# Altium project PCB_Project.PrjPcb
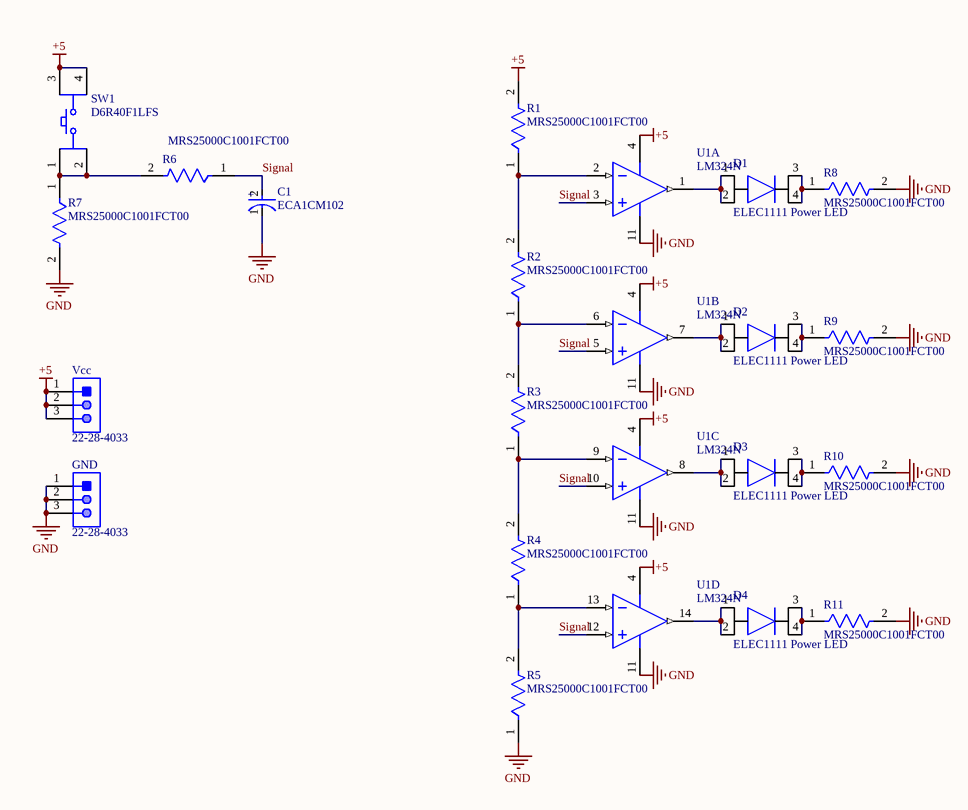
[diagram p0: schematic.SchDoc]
1 sheet, 20 parts. Net scope: global (net labels, ports and power ports of the same name join across sheets).

## Sheet schematic.SchDoc
size A4; SheetNumber: 1; SheetTotal: 1

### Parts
C1  ECA1CM102  [FP-RAD-TH-D_10_0_5-L_16_1-MFG]
D1  ELEC1111 Power LED  [ELEC1111_PowerLED]
D2  ELEC1111 Power LED  [ELEC1111_PowerLED]
D3  ELEC1111 Power LED  [ELEC1111_PowerLED]
D4  ELEC1111 Power LED  [ELEC1111_PowerLED]
GND  22-28-4033  [MOLX-22-28-4033_V]
R1  MRS25000C1001FCT00  [FP-MRS25-MFG]
R2  MRS25000C1001FCT00  [FP-MRS25-MFG]
R3  MRS25000C1001FCT00  [FP-MRS25-MFG]
R4  MRS25000C1001FCT00  [FP-MRS25-MFG]
R5  MRS25000C1001FCT00  [FP-MRS25-MFG]
R6  MRS25000C1001FCT00  [FP-MRS25-MFG]
R7  MRS25000C1001FCT00  [FP-MRS25-MFG]
R8  MRS25000C1001FCT00  [FP-MRS25-MFG]
R9  MRS25000C1001FCT00  [FP-MRS25-MFG]
R10  MRS25000C1001FCT00  [FP-MRS25-MFG]
R11  MRS25000C1001FCT00  [FP-MRS25-MFG]
SW1  D6R40F1LFS  [FP-D6R40F1LFS-MFG]
U1  LM324N  [N0014A]  (parts A,B,C,D of 4)
Vcc  22-28-4033  [MOLX-22-28-4033_V]

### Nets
+5: R1.2 SW1.3 SW1.4 U1.4(V+) Vcc.1 Vcc.2 Vcc.3
GND: C1.1(C) GND.1 GND.2 GND.3 R5.1 R7.2 R8.2 R9.2 R10.2 R11.2 U1.11(GND)
Signal: C1.2(A) R6.1 U1.3(IN1+) U1.5(IN2+) U1.10(IN3+) U1.12(IN4+)
NetD1_1: D1.1 D1.2 U1.1(OUT1)
NetD1_3: D1.3 D1.4 R8.1
NetD2_1: D2.1 D2.2 U1.7(OUT2)
NetD2_3: D2.3 D2.4 R9.1
NetD3_1: D3.1 D3.2 U1.8(OUT3)
NetD3_3: D3.3 D3.4 R10.1
NetD4_1: D4.1 D4.2 U1.14(OUT4)
NetD4_3: D4.3 D4.4 R11.1
NetR1_1: R1.1 R2.2 U1.2(IN1-)
NetR2_1: R2.1 R3.2 U1.6(IN2-)
NetR3_1: R3.1 R4.2 U1.9(IN3-)
NetR4_1: R4.1 R5.2 U1.13(IN4-)
NetR6_2: R6.2 R7.1 SW1.1 SW1.2

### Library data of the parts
C1 = CMP-05427-001524-1: Aluminum Electrolytic Capacitors (Radial Lead Type) 1000uF ±20% 16V; Life (Hours): 2000Hour; Ripple Current (AC): 680mA; Polarity: Polar; Lead/Base Style: Straight; Lead Diameter: 0.6mm; Capacitance: 1mF; Leakage Current: 3uA; Dissipation Factor: 0.2%
D1-D4 = ELEC1111 Power LED: An LED used in ELEC1111
GND Vcc = CMP-1676-00001-5: Male Header, Pitch 2.54 mm, 1 x 3 Position, Height 8.38 mm, Tail Length 3.18 mm, RoHS, Bulk; Manufacturer: Molex; Rows: 1; Voltage Rating: 250 V; Current Rating: 4 A
R1-R11 = CMP-02408-000051-1: RES 1K OHM 0.6W 1% AXIAL; Power Rating: 600mW; Lead Diameter: 0.6mm; Voltage Rating (DC): 350V; Resistance: 1kR; Temperature Coefficient: 50ppm/°C
SW1 = CMP-10035-000005-1: SWITCH PUSH SPST-NO 0.1A 32V; Switch Function: Off-Mom; Number of Poles: 1; Insulation Resistance: 100GR; Contact Resistance: 100mR; Actuator Length: 7mm; Row Spacing: 5mm; Max Current Rating: 100mA; Electrical Life: 250000Cycles; Number of Terminals/Pins: 4; Operating Force: 1.3N; Actuator Type: Round, Button; Throw Configuration: SPST; Actuator Color: Red; Illumination Type: Illuminated; Power Rating: 3W; Outside Diameter: 12mm; Voltage Rating (AC): 100V
U1 = CMP-0055-00082-3: Low Power Quad Operational Amplifier, 14-pin MDIP; Manufacturer: Texas Instruments; CompType: Amplifiers; PowerWise: N; PackageTopMarking: NSUZXYYTTE#*LM324N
